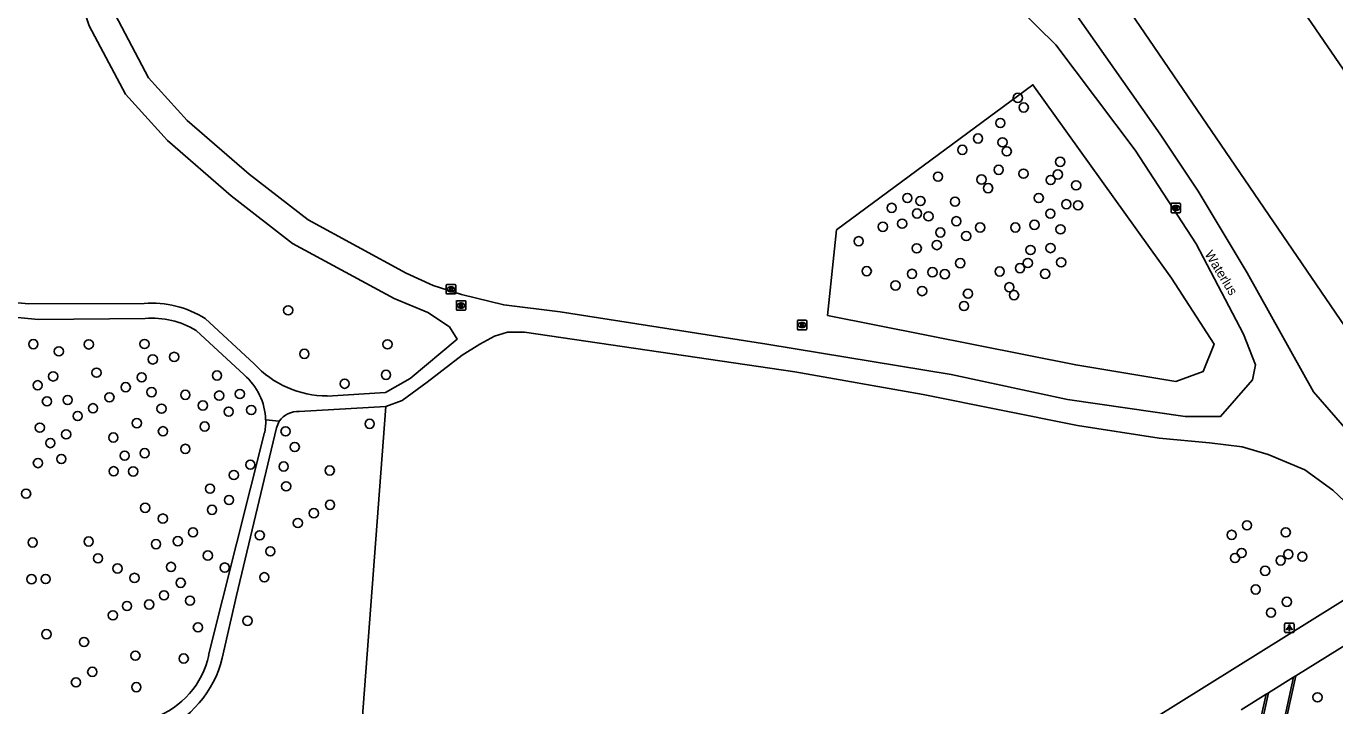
# Model space of a CAD drawing. Extents: x 155275 to 156263, y 382654 to 383635.
# Drawn here: x 155355.2 to 155494.7, y 383068.4 to 383140.8 of the extents above; entities that cross this region are included whole.
import ezdxf

# ---------------------------------------------------------------- set-up
doc = ezdxf.new("R2010")
doc.units = 0
for name, color, linetype in [('IMGEO_Boom', 7, 'Continuous'), ('IMGEO_Brandkraan', 7, 'Continuous'), ('IMGEO_Groenvoorziening', 7, 'Continuous'), ('IMGEO_Lichtpunt', 7, 'Continuous'), ('IMGEO_Openbare_ruimte_label', 7, 'Continuous'), ('IMGEO_Parkeervlak_open', 7, 'Continuous'), ('IMGEO_Rijbaan_lokaal_halfverhard', 7, 'Continuous'), ('IMGEO_Rioolput', 7, 'Continuous'), ('IMGEO_Voetpad_halfverhard', 7, 'Continuous'), ('IMGEO_Voetpad_open', 7, 'Continuous')]:
    doc.layers.add(name, color=color, linetype=linetype)

msp = doc.modelspace()

# ---------------------------------------------------------------- linework, layer by layer
at = {"layer": 'IMGEO_Boom'}
for centre in [(155460.88, 383133.17), (155461.51, 383132.15), (155459.02, 383130.49), (155456.64, 383128.84), (155459.25, 383128.43), (155454.96, 383127.63), (155459.7, 383127.47), (155465.39, 383126.36), (155458.83, 383125.51), (155461.48, 383125.09), (155465.14, 383125.01), (155452.37, 383124.78), (155457.01, 383124.47), (155457.71, 383123.55), (155464.37, 383124.43), (155467.09, 383123.86), (155449.11, 383122.5), (155450.5, 383122.18), (155454.19, 383122.11), (155463.11, 383122.51), (155447.44, 383121.45), (155450.14, 383120.85), (155464.34, 383120.84), (155466.04, 383121.84), (155467.3, 383121.72), (155446.49, 383119.44), (155448.55, 383119.77), (155451.36, 383120.55), (155454.32, 383120.03), (155456.86, 383119.36), (155460.61, 383119.36), (155462.65, 383119.65), (155443.92, 383117.9), (155452.62, 383118.83), (155455.38, 383118.45), (155465.43, 383119.17), (155450.11, 383117.15), (155452.25, 383117.49), (155462.23, 383116.97), (155464.36, 383117.17), (155454.74, 383115.56), (155461.95, 383115.58), (155465.5, 383115.66), (155444.78, 383114.71), (155449.61, 383114.42), (155451.78, 383114.6), (155453.1, 383114.39), (155458.94, 383114.68), (155461.11, 383115.03), (155463.79, 383114.43), (155447.84, 383113.19), (155450.68, 383112.59), (155455.56, 383112.31), (155459.97, 383113), (155455.15, 383111), (155460.48, 383112.16), (155383.13, 383110.54), (155355.98, 383106.94), (155361.88, 383106.91), (155367.82, 383106.96), (155393.71, 383106.92), (155358.69, 383106.17), (155370.98, 383105.58), (155384.85, 383105.9), (155368.7, 383105.31), (155356.44, 383102.56), (155358.09, 383103.5), (155362.7, 383103.9), (155367.52, 383103.4), (155375.55, 383103.6), (155389.14, 383102.72), (155393.56, 383103.67), (155364.08, 383101.28), (155365.82, 383102.35), (155368.57, 383101.83), (155372.17, 383101.54), (155375.78, 383101.46), (155377.98, 383101.63), (155357.42, 383100.84), (155359.63, 383100.99), (155362.33, 383100.11), (155369.63, 383100.07), (155374.04, 383100.4), (155376.78, 383099.75), (155379.19, 383099.93), (155360.7, 383099.28), (155367, 383098.52), (155391.81, 383098.45), (155356.66, 383098.05), (155359.47, 383097.33), (155364.49, 383096.99), (155369.78, 383097.66), (155374.23, 383098.16), (155382.85, 383097.65), (155357.78, 383096.4), (155372.17, 383095.78), (155383.83, 383095.98), (155356.46, 383094.27), (155358.96, 383094.71), (155365.7, 383095.06), (155367.83, 383095.32), (155364.53, 383093.4), (155366.61, 383093.38), (155377.34, 383093), (155379.09, 383094.1), (155382.65, 383093.9), (155387.56, 383093.48), (155374.79, 383091.55), (155382.91, 383091.8), (155355.2, 383091.01), (155376.82, 383090.33), (155367.89, 383089.51), (155375.01, 383089.29), (155385.86, 383088.93), (155387.59, 383089.82), (155369.77, 383088.36), (155384.16, 383087.89), (155485.3, 383087.64), (155355.9, 383085.81), (155361.87, 383085.92), (155371.37, 383085.95), (155372.99, 383086.89), (155380.1, 383086.58), (155483.66, 383086.62), (155489.43, 383086.89), (155369.04, 383085.64), (155374.57, 383084.42), (155381.22, 383084.87), (155484.73, 383084.7), (155489.7, 383084.56), (155362.87, 383084.12), (155364.94, 383083.04), (155370.64, 383083.21), (155376.37, 383083.14), (155484.03, 383084.16), (155488.89, 383083.89), (155491.2, 383084.31), (155355.78, 383081.9), (155357.29, 383081.92), (155366.75, 383082.04), (155380.58, 383082.11), (155487.23, 383082.79), (155371.68, 383081.52), (155486.23, 383080.81), (155365.96, 383079.04), (155368.31, 383079.21), (155369.9, 383080.19), (155372.66, 383079.61), (155489.54, 383079.49), (155364.45, 383078.06), (155378.79, 383077.47), (155487.85, 383078.33), (155357.37, 383076.05), (155373.51, 383076.77), (155361.38, 383075.21), (155366.85, 383073.76), (155372, 383073.45), (155362.25, 383072.03), (155360.51, 383070.91), (155366.94, 383070.4), (155492.81, 383069.32)]:
    msp.add_circle(centre, 0.489, dxfattribs=at)
at = {"layer": 'IMGEO_Brandkraan'}
for p, q in [((155437.4, 383108.55), (155437.4, 383109.41)), ((155437.47, 383109.48), (155438.32, 383109.48)), ((155437.88, 383109.26), (155437.91, 383109.26)), ((155437.91, 383108.7), (155437.88, 383108.7)), ((155438.4, 383109.41), (155438.4, 383108.55)), ((155438.32, 383108.48), (155437.47, 383108.48))]:
    msp.add_line(p, q, dxfattribs=at)
for points in [[(155437.4, 383108.55), (155437.4, 383109.41)], [(155437.47, 383109.48), (155438.32, 383109.48)], [(155437.74, 383109.18), (155437.74, 383108.78), (155437.96, 383108.78)], [(155437.97, 383109.18), (155437.74, 383109.18)], [(155437.92, 383109.1), (155437.87, 383109.1), (155437.87, 383109.02)], [(155437.87, 383109.02), (155437.92, 383109.02)], [(155437.93, 383108.95), (155437.87, 383108.95), (155437.87, 383108.86)], [(155437.87, 383108.86), (155437.93, 383108.86)], [(155438.4, 383109.41), (155438.4, 383108.55)], [(155438.32, 383108.48), (155437.47, 383108.48)]]:
    msp.add_lwpolyline(points, dxfattribs=at)
for centre, radius, start, end in [((155437.47, 383109.4), 0.0765, 91.552, 178.448), ((155437.47, 383109.4), 0.0765, 91.552, 178.448), ((155437.92, 383109.06), 0.0379, 267.8285, 90.9355), ((155437.93, 383108.91), 0.0404, 269.8759, 90.5077), ((155437.96, 383109.03), 0.251, 268.6676, 293.5347), ((155437.98, 383109.03), 0.145, 59.4692, 91.5367), ((155438, 383109.08), 0.0922, 285.5137, 58.1501), ((155438.01, 383108.89), 0.105, 301.3115, 78.989), ((155438.32, 383109.4), 0.0765, 1.552, 88.448), ((155438.32, 383109.4), 0.0765, 1.552, 88.448), ((155437.47, 383108.55), 0.0765, 181.552, 268.448), ((155437.47, 383108.55), 0.0765, 181.552, 268.448), ((155438.32, 383108.55), 0.0765, 271.552, 358.448), ((155438.32, 383108.55), 0.0765, 271.552, 358.448)]:
    msp.add_arc(centre, radius, start, end, dxfattribs=at)
for centre, major_axis, ratio, start_param, end_param in [((155437.88, 383108.98), (-0.387, 0.002), 0.722429, 4.712389, 7.853982), ((155437.91, 383108.98), (-0.39, 0.002), 0.717154, 1.570796, 4.712389)]:
    msp.add_ellipse(centre, major_axis=major_axis, ratio=ratio, start_param=start_param, end_param=end_param, dxfattribs=at)
at = {"layer": 'IMGEO_Groenvoorziening'}
for points in [[(155532.26, 383055.3), (155462.23, 383157.92)], [(155440.6, 383109.98), (155467.05, 383104.72), (155477.71, 383102.96), (155480.63, 383104.01), (155481.8, 383106.94), (155477.24, 383113.96), (155462.49, 383134.56), (155441.54, 383119.11), (155440.6, 383109.98)], [(155393.54, 383100.28), (155388.34, 383031.51)]]:
    msp.add_lwpolyline(points, dxfattribs=at)
at = {"layer": 'IMGEO_Lichtpunt'}
for p, q in [((155489.31, 383077.13), (155489.31, 383076.33)), ((155489.31, 383077.13), (155489.31, 383076.33)), ((155490.21, 383077.23), (155489.41, 383077.23)), ((155490.21, 383077.23), (155489.41, 383077.23)), ((155490.31, 383076.33), (155490.31, 383077.13)), ((155490.31, 383076.33), (155490.31, 383077.13)), ((155489.41, 383076.23), (155490.21, 383076.23)), ((155489.41, 383076.23), (155490.21, 383076.23))]:
    msp.add_line(p, q, dxfattribs=at)
for points in [[(155489.69, 383076.8), (155489.72, 383076.77), (155489.54, 383076.51), (155489.5, 383076.53), (155489.69, 383076.8)], [(155489.79, 383076.75), (155489.84, 383076.75), (155489.84, 383076.43), (155489.79, 383076.43), (155489.79, 383076.75)], [(155489.9, 383076.77), (155489.94, 383076.8), (155490.12, 383076.53), (155490.08, 383076.51), (155489.9, 383076.77)]]:
    msp.add_lwpolyline(points, dxfattribs=at)
msp.add_circle((155489.81, 383076.93), 0.0994, dxfattribs=at)
for centre, start, end in [((155489.41, 383077.13), 90, 180), ((155489.41, 383077.13), 90, 180), ((155490.21, 383077.13), 0, 90), ((155490.21, 383077.13), 0, 90), ((155489.41, 383076.33), 180, 270), ((155489.41, 383076.33), 180, 270), ((155490.21, 383076.33), 270, 0), ((155490.21, 383076.33), 270, 360)]:
    msp.add_arc(centre, 0.0946, start, end, dxfattribs=at)
at = {"layer": 'IMGEO_Parkeervlak_open'}
for points in [[(155490.26, 383071.47), (155487.79, 383060.18)], [(155489.51, 383067.11), (155490.49, 383071.62)], [(155485.1, 383058.5), (155487.59, 383069.81)], [(155487.35, 383069.66), (155486.04, 383063.73)]]:
    msp.add_lwpolyline(points, dxfattribs=at)
at = {"layer": 'IMGEO_Rijbaan_lokaal_halfverhard'}
for points in [[(155408.35, 383007.04), (155400.27, 383020.26), (155497.7, 383080.99)], [(155490.94, 383062.14), (155505.09, 383070.96), (155505.34, 383071.12), (155500.61, 383077.91), (155490.49, 383071.62)], [(155490.26, 383071.47), (155487.59, 383069.81)], [(155490.49, 383071.62), (155490.37, 383071.54), (155490.26, 383071.47)], [(155487.35, 383069.66), (155484.69, 383068)], [(155487.59, 383069.81), (155487.47, 383069.74), (155487.35, 383069.66)]]:
    msp.add_lwpolyline(points, dxfattribs=at)
at = {"layer": 'IMGEO_Rioolput'}
for p, q in [((155477.21, 383121.02), (155477.21, 383121.87)), ((155477.29, 383121.94), (155478.14, 383121.94)), ((155477.7, 383121.72), (155477.72, 383121.72)), ((155477.72, 383121.16), (155477.7, 383121.16)), ((155478.21, 383121.87), (155478.21, 383121.02)), ((155478.14, 383120.94), (155477.29, 383120.94)), ((155399.97, 383112.36), (155399.97, 383113.21)), ((155400.05, 383113.29), (155400.9, 383113.29)), ((155400.46, 383113.06), (155400.49, 383113.06)), ((155400.98, 383113.21), (155400.98, 383112.36)), ((155400.9, 383112.28), (155400.05, 383112.28)), ((155400.48, 383112.51), (155400.46, 383112.51)), ((155401.05, 383110.63), (155401.05, 383111.48)), ((155401.12, 383111.55), (155401.98, 383111.55)), ((155402.05, 383111.48), (155402.05, 383110.63)), ((155401.98, 383110.55), (155401.12, 383110.55)), ((155401.56, 383110.77), (155401.53, 383110.77)), ((155401.54, 383111.33), (155401.56, 383111.33))]:
    msp.add_line(p, q, dxfattribs=at)
for points in [[(155477.21, 383121.02), (155477.21, 383121.87)], [(155477.29, 383121.94), (155478.14, 383121.94)], [(155477.8, 383121.64), (155477.55, 383121.64), (155477.55, 383121.24)], [(155477.55, 383121.24), (155477.67, 383121.24), (155477.67, 383121.41), (155477.68, 383121.41)], [(155477.73, 383121.56), (155477.67, 383121.56), (155477.67, 383121.48)], [(155477.67, 383121.48), (155477.72, 383121.48)], [(155477.73, 383121.38), (155477.8, 383121.24), (155477.94, 383121.24), (155477.88, 383121.37)], [(155478.21, 383121.87), (155478.21, 383121.02)], [(155478.14, 383120.94), (155477.29, 383120.94)], [(155399.97, 383112.36), (155399.97, 383113.21)], [(155400.05, 383113.29), (155400.9, 383113.29)], [(155400.56, 383112.98), (155400.31, 383112.98), (155400.31, 383112.58)], [(155400.49, 383112.9), (155400.44, 383112.9), (155400.44, 383112.82)], [(155400.44, 383112.82), (155400.49, 383112.82)], [(155400.98, 383113.21), (155400.98, 383112.36)], [(155400.9, 383112.28), (155400.05, 383112.28)], [(155400.31, 383112.58), (155400.44, 383112.58), (155400.44, 383112.75), (155400.45, 383112.75)], [(155400.49, 383112.72), (155400.56, 383112.58), (155400.7, 383112.58), (155400.64, 383112.71)], [(155401.05, 383110.63), (155401.05, 383111.48)], [(155401.12, 383111.55), (155401.98, 383111.55)], [(155402.05, 383111.48), (155402.05, 383110.63)], [(155401.98, 383110.55), (155401.12, 383110.55)], [(155401.64, 383111.25), (155401.38, 383111.25), (155401.38, 383110.85)], [(155401.38, 383110.85), (155401.51, 383110.85), (155401.51, 383111.01), (155401.52, 383111.01)], [(155401.56, 383111.17), (155401.51, 383111.17), (155401.51, 383111.09)], [(155401.51, 383111.09), (155401.56, 383111.09)], [(155401.57, 383110.98), (155401.64, 383110.85), (155401.78, 383110.85), (155401.71, 383110.98)]]:
    msp.add_lwpolyline(points, dxfattribs=at)
for centre, radius, start, end in [((155477.29, 383121.87), 0.0765, 91.552, 178.448), ((155477.29, 383121.87), 0.0765, 91.552, 178.448), ((155477.68, 383121.35), 0.0533, 26.0293, 88.6989), ((155477.71, 383121.67), 0.19, 274.7715, 282.9687), ((155477.73, 383121.47), 0.0964, 77.0061, 93.1865), ((155477.75, 383121.52), 0.0378, 276.6634, 79.6772), ((155477.8, 383121.53), 0.109, 350.3612, 89.416), ((155477.8, 383121.53), 0.112, 277.5842, 350.9817), ((155477.78, 383121.32), 0.108, 29.5134, 73.7905), ((155478.14, 383121.87), 0.0765, 1.552, 88.448), ((155478.14, 383121.87), 0.0765, 1.552, 88.448), ((155477.29, 383121.02), 0.0765, 181.552, 268.448), ((155477.29, 383121.02), 0.0765, 181.552, 268.448), ((155478.14, 383121.02), 0.0765, 271.552, 358.448), ((155478.14, 383121.02), 0.0765, 271.552, 358.448), ((155400.05, 383113.21), 0.0765, 91.552, 178.448), ((155400.05, 383113.21), 0.0765, 91.552, 178.448), ((155400.49, 383112.81), 0.0964, 77.0061, 93.1865), ((155400.47, 383113.01), 0.19, 274.7715, 282.9687), ((155400.51, 383112.86), 0.0378, 276.6634, 79.6772), ((155400.56, 383112.87), 0.109, 350.3612, 89.416), ((155400.56, 383112.87), 0.112, 277.5842, 350.9817), ((155400.9, 383113.21), 0.0765, 1.552, 88.448), ((155400.9, 383113.21), 0.0765, 1.552, 88.448), ((155400.05, 383112.36), 0.0765, 181.552, 268.448), ((155400.05, 383112.36), 0.0765, 181.552, 268.448), ((155400.44, 383112.69), 0.0533, 26.0293, 88.6989), ((155400.54, 383112.66), 0.108, 29.5134, 73.7905), ((155400.9, 383112.36), 0.0765, 271.552, 358.448), ((155400.9, 383112.36), 0.0765, 271.552, 358.448), ((155401.12, 383111.48), 0.0765, 91.552, 178.448), ((155401.12, 383111.48), 0.0765, 91.552, 178.448), ((155401.97, 383111.48), 0.0765, 1.552, 88.448), ((155401.97, 383111.48), 0.0765, 1.552, 88.448), ((155401.12, 383110.63), 0.0765, 181.552, 268.448), ((155401.12, 383110.63), 0.0765, 181.552, 268.448), ((155401.52, 383110.96), 0.0533, 26.0293, 88.6989), ((155401.57, 383111.07), 0.0964, 77.0061, 93.1865), ((155401.55, 383111.28), 0.19, 274.7715, 282.9687), ((155401.58, 383111.13), 0.0378, 276.6634, 79.6772), ((155401.64, 383111.14), 0.109, 350.3612, 89.416), ((155401.63, 383111.14), 0.112, 277.5842, 350.9817), ((155401.62, 383110.92), 0.108, 29.5134, 73.7905), ((155401.97, 383110.63), 0.0765, 271.552, 358.448), ((155401.97, 383110.63), 0.0765, 271.552, 358.448)]:
    msp.add_arc(centre, radius, start, end, dxfattribs=at)
for centre, major_axis, ratio, start_param, end_param in [((155477.7, 383121.44), (-0.387, 0.002), 0.722429, 4.712389, 7.853982), ((155477.72, 383121.44), (-0.39, 0.002), 0.717154, 1.570796, 4.712389), ((155400.46, 383112.78), (-0.387, 0.002), 0.722429, 4.712389, 7.853982), ((155400.49, 383112.78), (-0.39, 0.002), 0.717154, 1.570796, 4.712389), ((155401.54, 383111.05), (-0.387, 0.002), 0.722429, 4.712389, 7.853982), ((155401.56, 383111.05), (-0.39, 0.002), 0.717154, 1.570796, 4.712389)]:
    msp.add_ellipse(centre, major_axis=major_axis, ratio=ratio, start_param=start_param, end_param=end_param, dxfattribs=at)
at = {"layer": 'IMGEO_Voetpad_halfverhard'}
for points in [[(155387.29, 383101.41), (155393.5, 383101.8), (155396.13, 383103.27), (155401.15, 383107.48), (155400.32, 383108.77), (155398, 383110.31), (155394.43, 383111.79), (155383.6, 383117.66), (155377.06, 383122.74), (155370.27, 383128.62), (155365.78, 383133.56), (155361.91, 383140.85), (155359.8, 383147.24), (155359.02, 383150.58), (155359.02, 383168.78), (155360.3, 383173.98), (155361.71, 383177.9), (155364.9, 383184), (155367.14, 383187.73), (155369.98, 383191.02), (155371.19, 383193.05), (155372.78, 383196.95)], [(155462.23, 383157.92), (155462.08, 383157.79), (155460.8, 383156.2), (155460.2, 383154.22), (155460.31, 383152.94), (155463.29, 383147.49), (155476.06, 383129.31), (155480.08, 383123.25), (155485.32, 383114.55), (155492.39, 383101.86), (155501.64, 383091.21)], [(155460.95, 383142.74), (155464.94, 383138.83), (155473.39, 383127.59), (155479.9, 383117.61), (155484.94, 383108), (155486.19, 383104.72), (155485.9, 383103.12), (155482.49, 383099.24), (155478.72, 383099.24), (155466.18, 383101.04), (155453.79, 383103.69), (155434.14, 383106.94), (155412.11, 383110.39), (155406.1, 383111.12), (155401.61, 383112.24), (155398.58, 383113.17), (155395.71, 383114.5), (155385.25, 383120.17), (155378.96, 383125.06), (155372.37, 383130.77), (155368.26, 383135.3), (155364.68, 383142.04)], [(155349.16, 383111.81), (155355.5, 383111.25), (155367.77, 383111.28)], [(155367.89, 383109.68), (155356.48, 383109.58), (155349.21, 383110.28)], [(155374.29, 383109.67), (155379.52, 383104.84)], [(155378.43, 383103.66), (155373.32, 383108.39)], [(155393.54, 383100.28), (155395.26, 383100.93), (155397.94, 383102.88), (155401.66, 383105.75), (155403.54, 383106.92), (155405.12, 383107.78), (155406.5, 383108.22), (155408.3, 383108.22), (155437.13, 383103.98), (155450.78, 383101.59), (155467.24, 383098.26), (155475.93, 383096.91), (155481.31, 383096.43), (155484.79, 383096.01), (155487.54, 383095.2), (155491.46, 383093.56), (155494.46, 383091.39), (155497.62, 383088.41)], [(155384.31, 383099.78), (155393.54, 383100.28)], [(155380.73, 383098.88), (155382.16, 383098.72)], [(155374.65, 383073.82), (155380.62, 383097.52)], [(155382.16, 383098.72), (155381.89, 383098.04), (155377.63, 383080.16), (155376.08, 383073.5)]]:
    msp.add_lwpolyline(points, dxfattribs=at)
for centre, radius, start, end in [((155368.57, 383100.5), 10.81, 58.0691, 94.2517), ((155368.57, 383100.49), 9.22, 58.989, 94.2431), ((155387.29, 383111.96), 10.54, 222.4807, 269.9956), ((155374.22, 383098.7), 6.51, 1.5857, 49.7196), ((155374.28, 383098.7), 6.46, 349.4798, 1.6068), ((155384.24, 383097.21), 2.57, 88.3524, 143.9444), ((155365.77, 383075.71), 9.09, 289.5801, 347.9592), ((155365.14, 383076.06), 11.24, 291.623, 346.8066)]:
    msp.add_arc(centre, radius, start, end, dxfattribs=at)
at = {"layer": 'IMGEO_Voetpad_open'}
msp.add_lwpolyline([(155477.83, 383162.13), (155480.03, 383158.88), (155521.54, 383098.33), (155531.27, 383084.39), (155531.33, 383084.3)], dxfattribs=at)

# ---------------------------------------------------------------- texts
at = {"layer": 'IMGEO_Openbare_ruimte_label'}
msp.add_text('Waterlus', height=1, rotation=301.4649, dxfattribs=at).set_placement((155480.75, 383116.53))

doc.saveas('drawing.dxf')
